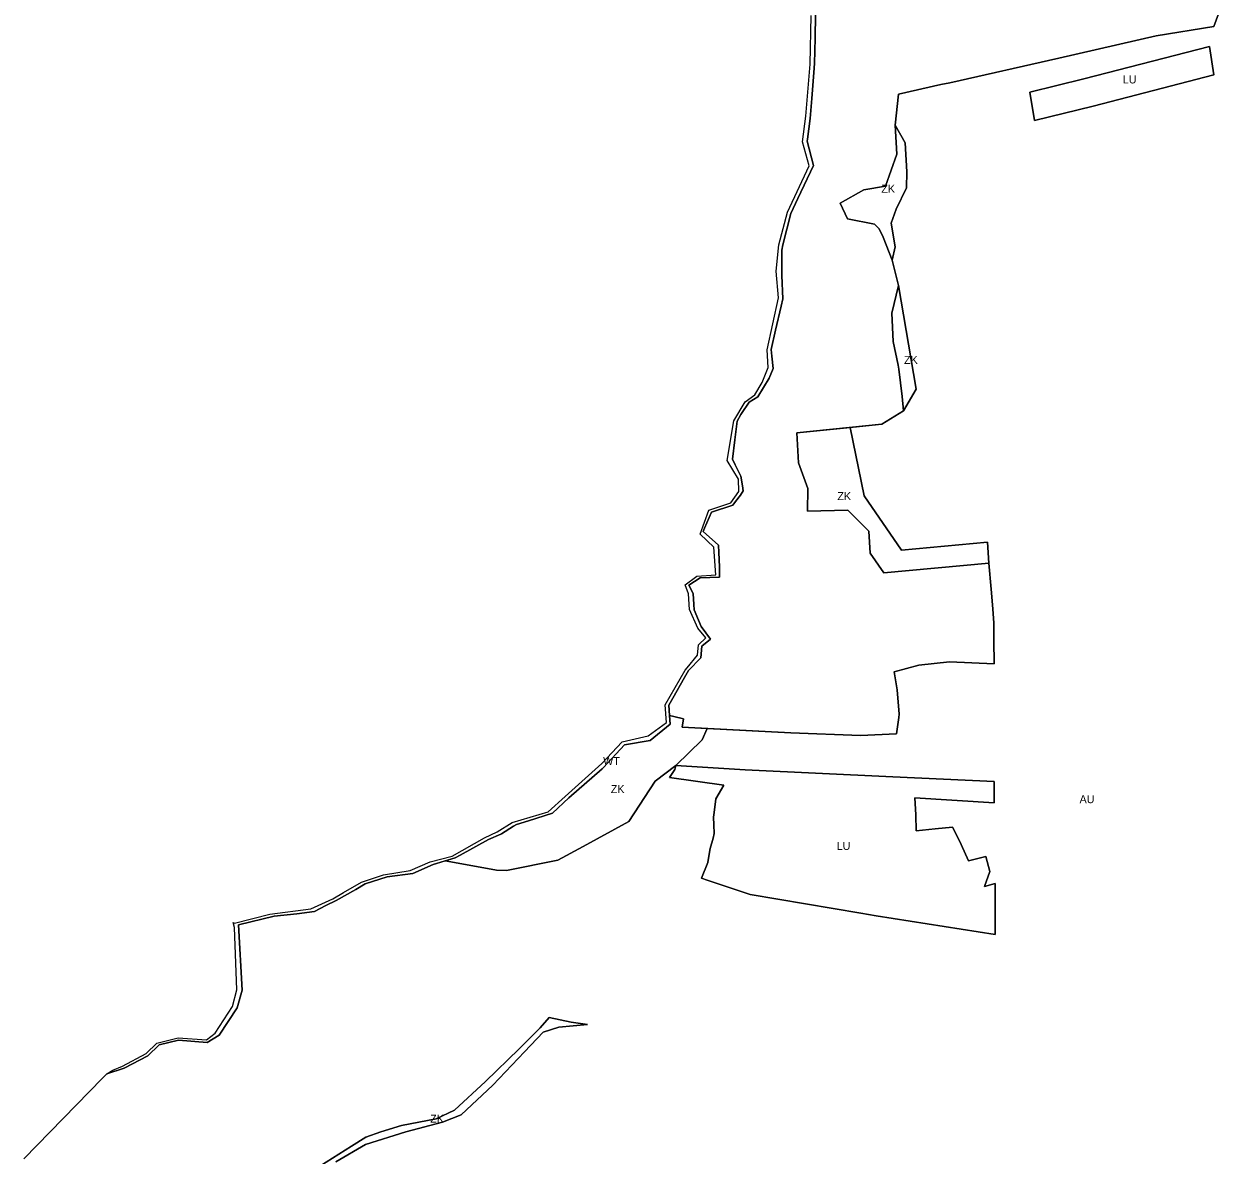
# Model space of a CAD drawing. Extents: x -541351 to -537540, y -1162694 to -1159725.
# Drawn here: x -541342 to -540593, y -1161126 to -1160420 of the extents above; entities that cross this region are included whole.
import ezdxf

# ---------------------------------------------------------------- set-up
doc = ezdxf.new("R2010")
doc.units = 0
for name, color, linetype in [('90640013', 7, 'Continuous'), ('90710013', 7, 'Continuous'), ('90750013', 7, 'Continuous'), ('90770013', 7, 'Continuous')]:
    doc.layers.add(name, color=color, linetype=linetype)

msp = doc.modelspace()

# ---------------------------------------------------------------- linework, layer by layer
at = {"layer": '90640013'}
msp.add_lwpolyline([(-540847.89, -1160414.07), (-540848.18, -1160428.76), (-540848.5, -1160444.54), (-540848.95, -1160450.24), (-540850.22, -1160466.43), (-540851.19, -1160478.87), (-540853.03, -1160491.9), (-540853.21, -1160493.19), (-540849.09, -1160508.25), (-540859.08, -1160528.97), (-540863.38, -1160538.23), (-540868.25, -1160557.92), (-540868.91, -1160561.29), (-540868.91, -1160576.98), (-540868.34, -1160591.53), (-540869.32, -1160596.18), (-540872.83, -1160611.2), (-540875.72, -1160623.23), (-540875.26, -1160627.34), (-540874.38, -1160635.18), (-540876.99, -1160641.09), (-540883.87, -1160652.81), (-540889.37, -1160656.16), (-540894.25, -1160663.31), (-540894.64, -1160663.92), (-540896.82, -1160668.04), (-540898.27, -1160679.74), (-540899.76, -1160691.7), (-540898.07, -1160695.2), (-540894.63, -1160702.3), (-540893.63, -1160708.4), (-540893.12, -1160711.56), (-540894.88, -1160714.31), (-540897.87, -1160718.26), (-540899.59, -1160720.53), (-540912.96, -1160724.74), (-540917.21, -1160734.89), (-540918.08, -1160736.97), (-540908.49, -1160745.39), (-540908.32, -1160749.94), (-540907.99, -1160759.02), (-540907.82, -1160765.33), (-540919.91, -1160765.89), (-540926.98, -1160770.35), (-540924.46, -1160775.65), (-540923.95, -1160782.5), (-540923.7, -1160785.88), (-540921, -1160792.33), (-540919.33, -1160796.31), (-540913.61, -1160804.14), (-540918.9, -1160808.46), (-540919.49, -1160815.78), (-540927.39, -1160823.69), (-540929.88, -1160828.15), (-540937.08, -1160841.04), (-540939.48, -1160845.34), (-540939.2, -1160851.88), (-540938.73, -1160857.26), (-540951.26, -1160867.4), (-540967.24, -1160870.15), (-540980.33, -1160884.28), (-540981.17, -1160885.14), (-541002.06, -1160903.18), (-541012.34, -1160912.92), (-541027.18, -1160917.57), (-541034.8, -1160920), (-541036.57, -1160920.93), (-541044.18, -1160925.64), (-541044.6, -1160925.92), (-541052.16, -1160929.36), (-541069.85, -1160939.12), (-541073.08, -1160940.82), (-541086.85, -1160944.98), (-541099.59, -1160950.61), (-541115.54, -1160952.68), (-541129.26, -1160956.98), (-541135.11, -1160960.45), (-541147.43, -1160967.41), (-541153.86, -1160970.54), (-541161.06, -1160974.14), (-541172.1, -1160975.69), (-541186.08, -1160977.09), (-541208.35, -1160982.65), (-541206.24, -1161023.44), (-541209.3, -1161034.42), (-541220.56, -1161051.38), (-541228.07, -1161056.14), (-541245.99, -1161054.69), (-541258.08, -1161057.42), (-541265.15, -1161064.43), (-541279.94, -1161072.09), (-541290.67, -1161075.6), (-541287.06, -1161073.27), (-541281.01, -1161070.85), (-541266.14, -1161062.85), (-541259.37, -1161056.48), (-541246.23, -1161053.24), (-541228.36, -1161054.44), (-541223, -1161050.33), (-541212.21, -1161033.59), (-541209.46, -1161023.23), (-541211, -1160984.28), (-541211.78, -1160981.11), (-541210.84, -1160981.54), (-541188.83, -1160975.83), (-541163.17, -1160972.48), (-541149.48, -1160966.42), (-541142.81, -1160962.39), (-541131.61, -1160955.96), (-541117.84, -1160951.35), (-541101.16, -1160948.65), (-541088.68, -1160943.22), (-541074.96, -1160939.7), (-541054.72, -1160928.23), (-541046.74, -1160924.48), (-541037.53, -1160918.75), (-541015.05, -1160912.07), (-541004.31, -1160902.35), (-540981.39, -1160881.88), (-540968.74, -1160868.27), (-540952.45, -1160864.6), (-540941.04, -1160856.18), (-540941.79, -1160845.2), (-540929.37, -1160823.59), (-540928.15, -1160822.01), (-540921.76, -1160814.24), (-540921.1, -1160807.76), (-540916.4, -1160803.22), (-540921.47, -1160797.25), (-540926.57, -1160785.66), (-540927.28, -1160775.78), (-540929.44, -1160770.22), (-540922.07, -1160764.9), (-540910.26, -1160764.01), (-540911.42, -1160746.8), (-540919.92, -1160738.52), (-540914.63, -1160723.57), (-540900.76, -1160719.02), (-540895.75, -1160711.83), (-540896.14, -1160704.26), (-540903.05, -1160692.48), (-540899.02, -1160667.81), (-540891.8, -1160655.88), (-540885.88, -1160651.59), (-540881.31, -1160643.94), (-540877.54, -1160634.39), (-540878.1, -1160623.35), (-540871.02, -1160591.04), (-540872.59, -1160574.32), (-540870.95, -1160557.89), (-540865.49, -1160537.48), (-540851.88, -1160508.48), (-540856.16, -1160493.51), (-540853.95, -1160477.46), (-540851.22, -1160445), (-540850.56, -1160414.55)], dxfattribs=at)
at = {"layer": '90710013'}
for points in [[(-540800, -1160567.48), (-540805.57, -1160553.03), (-540808.15, -1160547.85), (-540811.17, -1160545.07), (-540828.05, -1160541.69), (-540832.5, -1160531.81), (-540817.64, -1160523.43), (-540804.31, -1160521.27), (-540797.1, -1160501.26), (-540798.1, -1160483.18), (-540791.904, -1160494.203), (-540790.93, -1160512.189), (-540791.121, -1160522.327), (-540797.561, -1160535.571), (-540800.691, -1160544.251), (-540798.187, -1160559.105)], [(-540792.94, -1160661.5), (-540793.84, -1160652.65), (-540795.98, -1160635.63), (-540796.31, -1160633.04), (-540799.49, -1160618.19), (-540800.21, -1160600.46), (-540796.08, -1160583.18), (-540784.982, -1160648.083)], [(-540739.73, -1160756.66), (-540805.25, -1160762.67), (-540813.8, -1160750.47), (-540814.64, -1160736.75), (-540827.83, -1160723.53), (-540852.85, -1160724.16), (-540852.69, -1160710.11), (-540858.65, -1160694.1), (-540859.62, -1160675.32), (-540826.208, -1160671.944), (-540817.608, -1160714.613), (-540794.131, -1160748.622), (-540740.47, -1160743.58)], [(-541050.606, -1160947.898), (-541079.277, -1160942.692), (-541079.277, -1160942.692), (-541073.08, -1160940.82), (-541069.85, -1160939.12), (-541052.16, -1160929.36), (-541044.6, -1160925.92), (-541044.18, -1160925.64), (-541036.57, -1160920.93), (-541034.8, -1160920), (-541027.18, -1160917.57), (-541012.34, -1160912.92), (-541002.06, -1160903.18), (-540981.17, -1160885.14), (-540980.33, -1160884.28), (-540967.24, -1160870.15), (-540951.26, -1160867.4), (-540938.73, -1160857.26), (-540939.2, -1160851.88), (-540936.46, -1160852.48), (-540930.39, -1160853.92), (-540931.25, -1160859.15), (-540915.652, -1160859.95), (-540918.686, -1160866.945), (-540935.25, -1160883), (-540948.112, -1160892.785), (-540964.49, -1160918.11), (-540993.197, -1160933.586), (-541008.985, -1160942.098), (-541041.01, -1160948.67), (-541047.212, -1160948.514)]]:
    msp.add_lwpolyline(points, close=True, dxfattribs=at)
msp.add_lwpolyline([(-541165.46, -1161138.22), (-541137.93, -1161120.85), (-541128.8, -1161115.18), (-541119.44, -1161111.8), (-541106.61, -1161107.88), (-541095.72, -1161105.75), (-541084.97, -1161103.63), (-541073.5, -1161098.28), (-541054.13, -1161080.42), (-541033.05, -1161060.07), (-541028.84, -1161055.79), (-541019.98, -1161046.9), (-541014.34, -1161040.54), (-541000.52, -1161043.31), (-540990.48, -1161044.81), (-541008.267, -1161046.532), (-541018.031, -1161049.69), (-541029.668, -1161061.826), (-541049.621, -1161082.636), (-541069.411, -1161101.197), (-541081.048, -1161105.834), (-541103.928, -1161111.952), (-541129.064, -1161119.717), (-541147.693, -1161130.687)], dxfattribs=at)
at = {"layer": '90750013'}
for points in [[(-541342.47, -1161128.62), (-541293.38, -1161078.37), (-541290.67, -1161075.6), (-541279.94, -1161072.09), (-541265.15, -1161064.43), (-541258.08, -1161057.42), (-541245.99, -1161054.69), (-541228.07, -1161056.14), (-541220.56, -1161051.38), (-541209.3, -1161034.42), (-541206.24, -1161023.44), (-541208.35, -1160982.65), (-541186.08, -1160977.09), (-541172.1, -1160975.69), (-541161.06, -1160974.14), (-541153.86, -1160970.54), (-541147.43, -1160967.41), (-541135.11, -1160960.45), (-541129.26, -1160956.98), (-541115.54, -1160952.68), (-541099.59, -1160950.61), (-541086.85, -1160944.98), (-541079.277, -1160942.692), (-541050.606, -1160947.898), (-541047.212, -1160948.514), (-541041.01, -1160948.67), (-541008.985, -1160942.098), (-540993.197, -1160933.586), (-540964.49, -1160918.11), (-540948.112, -1160892.785), (-540935.25, -1160883), (-540935.75, -1160885.53), (-540939.11, -1160890.53), (-540905.15, -1160895.35), (-540910.19, -1160903.8), (-540911.33, -1160912.35), (-540911.72, -1160915.24), (-540911.45, -1160920.09), (-540911.15, -1160925.59), (-540911.97, -1160928.4), (-540913.85, -1160934.84), (-540915.07, -1160942.26), (-540915.29, -1160943.61), (-540919.24, -1160953.34), (-540915.61, -1160954.58), (-540888.86, -1160963.71), (-540819.65, -1160975.28), (-540810.09, -1160976.9), (-540735.73, -1160988.61), (-540735.72, -1160987.66), (-540735.78, -1160969.51), (-540735.79, -1160959.64), (-540735.79, -1160956.76), (-540742.25, -1160958.57), (-540739.08, -1160949.21), (-540741.43, -1160939.83), (-540752.32, -1160942.65), (-540756.88, -1160932.5), (-540761.61, -1160923.03), (-540762.31, -1160921.62), (-540773.18, -1160922.67), (-540785, -1160923.82), (-540785.33, -1160913.91), (-540785.97, -1160903.3), (-540736.22, -1160906.29), (-540736.28, -1160893.08), (-540799.66, -1160890.04), (-540891.91, -1160885.78), (-540935.25, -1160883), (-540918.686, -1160866.945), (-540915.652, -1160859.95), (-540863.38, -1160862.63), (-540819.89, -1160864.31), (-540797.32, -1160863.3), (-540795.91, -1160853.02), (-540795.64, -1160851.02), (-540797, -1160835.7), (-540798.89, -1160824.47), (-540783.37, -1160820.48), (-540764.18, -1160818.28), (-540736.36, -1160819.57), (-540736.47, -1160804.87), (-540736.46, -1160794.17), (-540737.2, -1160785.2), (-540738.29, -1160772.93), (-540739.73, -1160756.66), (-540740.47, -1160743.58), (-540794.131, -1160748.622), (-540817.608, -1160714.613), (-540826.208, -1160671.944), (-540826.208, -1160671.944), (-540806.57, -1160669.96), (-540792.94, -1160661.5), (-540784.982, -1160648.083), (-540796.08, -1160583.18), (-540800, -1160567.48), (-540798.187, -1160559.105), (-540800.691, -1160544.251), (-540797.561, -1160535.571), (-540791.121, -1160522.327), (-540790.93, -1160512.189), (-540791.904, -1160494.203), (-540798.1, -1160483.18), (-540796.15, -1160463.78), (-540769.64, -1160457.75), (-540763.94, -1160456.69), (-540695.98, -1160441.23), (-540635.02, -1160427.41), (-540599.1, -1160421.48), (-540593.33, -1160405.59)], [(-541147.693, -1161130.687), (-541129.064, -1161119.717), (-541103.928, -1161111.952), (-541081.048, -1161105.834), (-541069.411, -1161101.197), (-541049.621, -1161082.636), (-541029.668, -1161061.826), (-541018.031, -1161049.69), (-541008.267, -1161046.532), (-540990.48, -1161044.81), (-541000.52, -1161043.31), (-541014.34, -1161040.54), (-541019.98, -1161046.9), (-541028.84, -1161055.79), (-541033.05, -1161060.07), (-541054.13, -1161080.42), (-541073.5, -1161098.28), (-541084.97, -1161103.63), (-541095.72, -1161105.75), (-541106.61, -1161107.88), (-541119.44, -1161111.8), (-541128.8, -1161115.18), (-541137.93, -1161120.85), (-541165.46, -1161138.22)]]:
    msp.add_lwpolyline(points, dxfattribs=at)
msp.add_lwpolyline([(-540599.16, -1160451.77), (-540601.74, -1160433.96), (-540680.28, -1160454.15), (-540714.13, -1160462.45), (-540711.15, -1160480.18), (-540674.45, -1160471.22)], close=True, dxfattribs=at)
at = {"layer": '90770013'}
msp.add_lwpolyline([(-540593.33, -1160405.59), (-540599.1, -1160421.48), (-540635.02, -1160427.41), (-540695.98, -1160441.23), (-540763.94, -1160456.69), (-540769.64, -1160457.75), (-540796.15, -1160463.78), (-540798.1, -1160483.18), (-540797.1, -1160501.26), (-540804.31, -1160521.27), (-540817.64, -1160523.43), (-540832.5, -1160531.81), (-540828.05, -1160541.69), (-540811.17, -1160545.07), (-540808.15, -1160547.85), (-540805.57, -1160553.03), (-540800, -1160567.48), (-540796.08, -1160583.18), (-540800.21, -1160600.46), (-540799.49, -1160618.19), (-540796.31, -1160633.04), (-540795.98, -1160635.63), (-540793.84, -1160652.65), (-540792.94, -1160661.5), (-540806.57, -1160669.96), (-540859.62, -1160675.32), (-540858.65, -1160694.1), (-540852.69, -1160710.11), (-540852.85, -1160724.16), (-540827.83, -1160723.53), (-540814.64, -1160736.75), (-540813.8, -1160750.47), (-540805.25, -1160762.67), (-540739.73, -1160756.66), (-540738.29, -1160772.93), (-540737.2, -1160785.2), (-540736.46, -1160794.17), (-540736.47, -1160804.87), (-540736.36, -1160819.57), (-540764.18, -1160818.28), (-540783.37, -1160820.48), (-540798.89, -1160824.47), (-540797, -1160835.7), (-540795.64, -1160851.02), (-540795.91, -1160853.02), (-540797.32, -1160863.3), (-540819.89, -1160864.31), (-540863.38, -1160862.63), (-540931.25, -1160859.15), (-540930.39, -1160853.92), (-540936.46, -1160852.48), (-540939.2, -1160851.88), (-540939.48, -1160845.34), (-540937.08, -1160841.04), (-540929.88, -1160828.15), (-540927.39, -1160823.69), (-540919.49, -1160815.78), (-540918.9, -1160808.46), (-540913.61, -1160804.14), (-540919.33, -1160796.31), (-540921, -1160792.33), (-540923.7, -1160785.88), (-540923.95, -1160782.5), (-540924.46, -1160775.65), (-540926.98, -1160770.35), (-540919.91, -1160765.89), (-540907.82, -1160765.33), (-540907.99, -1160759.02), (-540908.32, -1160749.94), (-540908.49, -1160745.39), (-540918.08, -1160736.97), (-540917.21, -1160734.89), (-540912.96, -1160724.74), (-540899.59, -1160720.53), (-540897.87, -1160718.26), (-540894.88, -1160714.31), (-540893.12, -1160711.56), (-540893.63, -1160708.4), (-540894.63, -1160702.3), (-540898.07, -1160695.2), (-540899.76, -1160691.7), (-540898.27, -1160679.74), (-540896.82, -1160668.04), (-540894.64, -1160663.92), (-540894.25, -1160663.31), (-540889.37, -1160656.16), (-540883.87, -1160652.81), (-540876.99, -1160641.09), (-540874.38, -1160635.18), (-540875.26, -1160627.34), (-540875.72, -1160623.23), (-540872.83, -1160611.2), (-540869.32, -1160596.18), (-540868.34, -1160591.53), (-540868.91, -1160576.98), (-540868.91, -1160561.29), (-540868.25, -1160557.92), (-540863.38, -1160538.23), (-540859.08, -1160528.97), (-540849.09, -1160508.25), (-540853.21, -1160493.19), (-540853.03, -1160491.9), (-540851.19, -1160478.87), (-540850.22, -1160466.43), (-540848.95, -1160450.24), (-540848.5, -1160444.54), (-540848.18, -1160428.76), (-540847.89, -1160414.07)], dxfattribs=at)
for points in [[(-540599.16, -1160451.77), (-540674.45, -1160471.22), (-540711.15, -1160480.18), (-540714.13, -1160462.45), (-540680.28, -1160454.15), (-540601.74, -1160433.96)], [(-540799.66, -1160890.04), (-540736.28, -1160893.08), (-540736.22, -1160906.29), (-540785.97, -1160903.3), (-540785.33, -1160913.91), (-540785, -1160923.82), (-540773.18, -1160922.67), (-540762.31, -1160921.62), (-540761.61, -1160923.03), (-540756.88, -1160932.5), (-540752.32, -1160942.65), (-540741.43, -1160939.83), (-540739.08, -1160949.21), (-540742.25, -1160958.57), (-540735.79, -1160956.76), (-540735.79, -1160959.64), (-540735.78, -1160969.51), (-540735.72, -1160987.66), (-540735.73, -1160988.61), (-540810.09, -1160976.9), (-540819.65, -1160975.28), (-540888.86, -1160963.71), (-540915.61, -1160954.58), (-540919.24, -1160953.34), (-540915.29, -1160943.61), (-540915.07, -1160942.26), (-540913.85, -1160934.84), (-540911.97, -1160928.4), (-540911.15, -1160925.59), (-540911.45, -1160920.09), (-540911.72, -1160915.24), (-540911.33, -1160912.35), (-540910.19, -1160903.8), (-540905.15, -1160895.35), (-540939.11, -1160890.53), (-540935.75, -1160885.53), (-540935.25, -1160883), (-540891.91, -1160885.78)]]:
    msp.add_lwpolyline(points, close=True, dxfattribs=at)

# ---------------------------------------------------------------- texts
at = {"layer": '90640013'}
msp.add_text('WT', height=5, rotation=360, dxfattribs=at).set_placement((-540980.58, -1160882.772))
at = {"layer": '90710013'}
for rotation, p in [(0, (-540806.795, -1160525.33)), (0, (-540792.596, -1160632.238)), (0, (-540834.26, -1160717.307)), (360, (-540975.826, -1160900.275)), (0, (-541088.665, -1161106.115))]:
    msp.add_text('ZK', height=5, rotation=rotation, dxfattribs=at).set_placement(p)
at = {"layer": '90750013'}
msp.add_text('AU', height=5, rotation=360, dxfattribs=at).set_placement((-540682.952, -1160906.585))
at = {"layer": '90770013'}
for p in [(-540655.932, -1160457.07), (-540834.702, -1160935.805)]:
    msp.add_text('LU', height=5, rotation=360, dxfattribs=at).set_placement(p)

doc.saveas('drawing.dxf')
